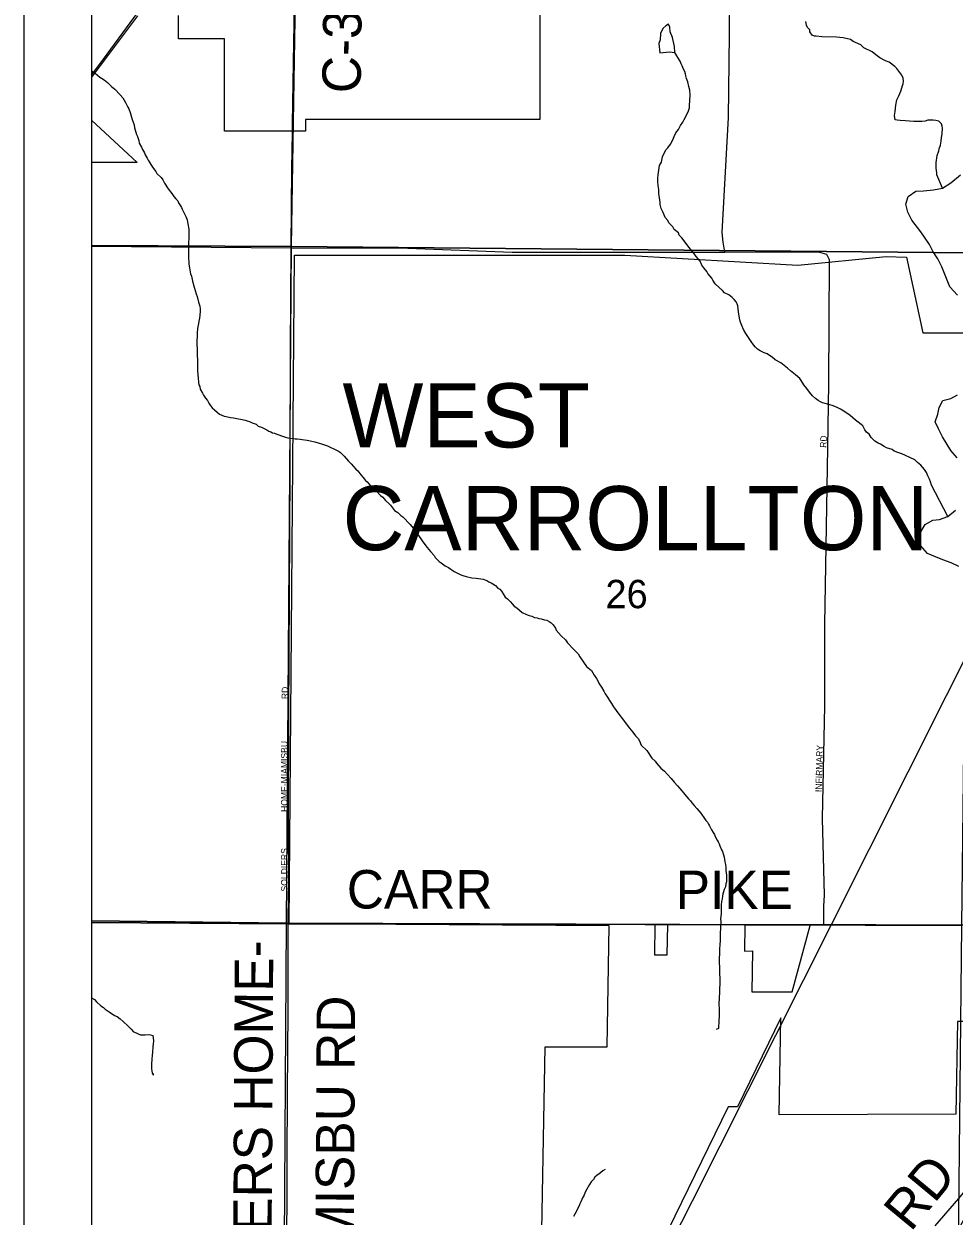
# Model space of a CAD drawing. Extents: x -209 to 4852, y 0 to 905.
# Drawn here: x 433.77 to 461.25, y 254.75 to 289.97 of the extents above; entities that cross this region are included whole.
import ezdxf

# ---------------------------------------------------------------- set-up
doc = ezdxf.new("R2010")
doc.units = 0
for name, color, linetype in [('Default', 7, 'Continuous'), ('GM_P_County_Alignment', 7, 'Continuous'), ('GM_X_Airport_Location_Class_2', 7, 'Continuous'), ('GM_X_Airport_Location_Class_3', 7, 'Continuous'), ('GM_X_Corporation_Text', 7, 'Continuous'), ('GM_X_County_Road', 7, 'Continuous'), ('GM_X_County_Road_Text', 7, 'Continuous'), ('GM_X_County_Subdivision_Text', 7, 'Continuous'), ('GM_X_Minor_Lake_Text', 7, 'Continuous'), ('GM_X_Minor_River', 7, 'Continuous'), ('GM_X_Township_Road_Text', 7, 'Continuous'), ('GM_X_US_Location', 7, 'Continuous'), ('GM_X_US_Route', 7, 'Continuous'), ('SH_Data', 7, 'Continuous')]:
    doc.layers.add(name, color=color, linetype=linetype)

msp = doc.modelspace()

# ---------------------------------------------------------------- linework, layer by layer
at = {"layer": 'Default'}
msp.add_lwpolyline([(571.768, 202.559), (571.768, 338.559), (435.768, 338.559), (435.768, 202.559)], close=True, dxfattribs=at)
at = {"layer": 'GM_X_Airport_Location_Class_2'}
for points in [[(454.478, 283.232), (454.434, 283.528), (454.404, 283.81), (454.583, 287.205), (454.62, 289.656), (454.639, 291.955), (454.657, 293.282), (454.655, 293.317)], [(441.671, 283.356), (441.689, 285.704), (441.706, 286.766)], [(435.768, 283.404), (441.671, 283.356), (445.118, 283.344), (448.196, 283.232), (451.618, 283.226), (454.478, 283.232)], [(441.582, 263.588), (441.598, 264.63), (441.587, 266.284), (441.602, 269.525), (441.62, 273.113), (441.632, 276.804), (441.647, 280.335), (441.671, 283.356)], [(457.569, 282.996), (457.569, 283.005), (457.496, 283.158), (457.285, 283.224), (454.478, 283.232)], [(457.401, 263.358), (457.408, 263.906), (457.422, 264.232), (457.369, 266.498), (457.429, 269.826), (457.431, 272.243), (457.481, 275.123), (457.519, 277.448), (457.554, 279.348), (457.569, 282.985), (457.569, 282.996)], [(457.401, 263.358), (464.729, 263.345)]]:
    msp.add_lwpolyline(points, dxfattribs=at)
at = {"layer": 'GM_X_County_Road'}
for points in [[(452.847, 289.145), (453.006, 289.127), (452.994, 289.302), (452.931, 289.569), (452.859, 289.738), (452.854, 289.875), (452.818, 289.967), (452.733, 289.916), (452.647, 289.834), (452.576, 289.69)], [(460.91, 285.12), (460.741, 285.517), (460.742, 285.578), (460.736, 285.632), (460.723, 285.723), (460.718, 285.815), (460.72, 285.876), (460.729, 285.944), (460.746, 286.005), (460.756, 286.081), (460.805, 286.225), (460.814, 286.278), (460.847, 286.391), (460.866, 286.513), (460.884, 286.619), (460.902, 286.725), (460.906, 286.893), (460.9, 286.954), (460.879, 287.023), (460.797, 287.102), (460.714, 287.119), (460.63, 287.128), (460.554, 287.13), (460.478, 287.124), (460.393, 287.104), (460.301, 287.091), (460.195, 287.086), (460.065, 287.089), (459.936, 287.099), (459.814, 287.11), (459.662, 287.114), (459.57, 287.131), (459.51, 287.14), (459.49, 287.263), (459.508, 287.384), (459.528, 287.567), (459.563, 287.734), (459.62, 287.847), (459.676, 287.983), (459.726, 288.149), (459.751, 288.202), (459.76, 288.285), (459.747, 288.37), (459.711, 288.454), (459.653, 288.54), (459.564, 288.656), (459.497, 288.711), (459.333, 288.845), (459.227, 288.885), (459.062, 288.973), (458.942, 289.06), (458.83, 289.147), (458.589, 289.267), (458.5, 289.353), (458.266, 289.457), (458.191, 289.513), (457.971, 289.564), (457.781, 289.584), (457.347, 289.594), (457.18, 289.613), (457.126, 289.615), (457.058, 289.639), (456.992, 289.74), (456.986, 289.793), (456.919, 289.864), (456.891, 289.933), (456.871, 290.04)], [(452.576, 289.69), (452.572, 289.5), (452.532, 289.395), (452.557, 289.113), (452.847, 289.145)], [(452.568, 284.64), (452.57, 284.693), (452.556, 284.77), (452.531, 284.961), (452.532, 285.014), (452.526, 285.076), (452.506, 285.198), (452.502, 285.32), (452.497, 285.412), (452.507, 285.511), (452.535, 285.716), (452.552, 285.792), (452.608, 285.889), (452.617, 285.95), (452.642, 286.041), (452.739, 286.252), (452.794, 286.312), (452.873, 286.417), (452.945, 286.544), (452.986, 286.643), (453.035, 286.756), (453.113, 286.853), (453.17, 286.974), (453.241, 287.071), (453.273, 287.146), (453.362, 287.312), (453.41, 287.402), (453.435, 287.493), (453.437, 287.562), (453.448, 287.706), (453.452, 287.874), (453.441, 288.011), (453.413, 288.119), (453.386, 288.257), (453.351, 288.364), (453.33, 288.441), (453.316, 288.495), (453.295, 288.564), (453.258, 288.633), (453.215, 288.733), (453.186, 288.795), (453.165, 288.849), (453.006, 289.127)], [(435.768, 288.597), (435.797, 288.569), (435.872, 288.513), (436.014, 288.403), (436.067, 288.371), (436.142, 288.324), (436.239, 288.238), (436.358, 288.12), (436.455, 288.042), (436.611, 287.878), (436.692, 287.785), (436.773, 287.653), (436.838, 287.514), (436.867, 287.46), (436.91, 287.352), (436.965, 287.153), (437.03, 286.991)], [(437.03, 286.991), (437.035, 286.907), (437.078, 286.777), (437.099, 286.708), (437.128, 286.646), (437.163, 286.531), (437.176, 286.454), (437.242, 286.331), (437.27, 286.261), (437.329, 286.168), (437.35, 286.107), (437.409, 286.006), (437.438, 285.952), (437.489, 285.867), (437.569, 285.743), (437.665, 285.611), (437.702, 285.55), (437.828, 285.44), (437.872, 285.362), (437.923, 285.27), (438.033, 285.099), (438.136, 284.96), (438.203, 284.874), (438.254, 284.804), (438.314, 284.742), (438.335, 284.688), (438.401, 284.603), (438.431, 284.549), (438.444, 284.495), (438.488, 284.425), (438.553, 284.279), (438.589, 284.186), (438.616, 284.071), (438.643, 283.911), (438.646, 283.743), (438.643, 283.621), (438.633, 283.522), (438.637, 283.4), (438.632, 283.187), (438.637, 283.103), (438.635, 283.034), (438.641, 282.95), (438.646, 282.874), (438.667, 282.767), (438.693, 282.591), (438.721, 282.521), (438.748, 282.368), (438.797, 282.199), (438.86, 282), (438.889, 281.923), (438.93, 281.754), (438.965, 281.631), (438.978, 281.555), (438.976, 281.471), (438.956, 281.281), (438.938, 281.19), (438.929, 281.121), (438.902, 280.977), (438.891, 280.833), (438.883, 280.513), (438.886, 280.36), (438.885, 280.307), (438.888, 280.139), (438.895, 280.086), (438.899, 279.948), (438.897, 279.895), (438.901, 279.758), (438.912, 279.59), (438.918, 279.513), (438.93, 279.383), (438.943, 279.314), (438.965, 279.261), (438.978, 279.184), (439.051, 279.06), (439.08, 279.006), (439.131, 278.921), (439.19, 278.843), (439.234, 278.766), (439.271, 278.712), (439.337, 278.634), (439.397, 278.572), (439.479, 278.501), (439.546, 278.446), (439.682, 278.389), (439.742, 278.373), (439.871, 278.347), (439.962, 278.337), (440.114, 278.31), (440.167, 278.301), (440.311, 278.267), (440.364, 278.251), (440.44, 278.226), (440.515, 278.186), (440.628, 278.145), (440.696, 278.09), (440.794, 278.057), (440.846, 278.026), (440.952, 277.977), (441.004, 277.946), (441.065, 277.921), (441.118, 277.897)], [(461.356, 281.956), (461.127, 282.206), (460.892, 282.799), (460.776, 283.031), (460.637, 283.24), (460.529, 283.456), (460.273, 283.829), (460.008, 284.179), (459.885, 284.411), (459.831, 284.648), (459.898, 284.875), (460.123, 285.036), (460.344, 285.037), (460.642, 285.067), (460.91, 285.12), (461.157, 285.273), (461.446, 285.509)], [(461.071, 275.426), (460.588, 276.348), (460.552, 276.441), (460.523, 276.525), (460.48, 276.626), (460.437, 276.718), (460.378, 276.811), (460.319, 276.881), (460.267, 276.936), (460.17, 277.014), (460.096, 277.092), (459.945, 277.165), (459.817, 277.221), (459.704, 277.27), (459.621, 277.302), (459.485, 277.351), (459.425, 277.398), (459.251, 277.448), (459.191, 277.488), (459.079, 277.559), (459.011, 277.591), (458.913, 277.647), (458.802, 277.757), (458.743, 277.857), (458.669, 277.912), (458.617, 277.982), (458.559, 278.098), (458.507, 278.137), (458.417, 278.208), (458.342, 278.271), (458.26, 278.334), (458.178, 278.405), (457.998, 278.531), (457.901, 278.587), (457.795, 278.643), (457.675, 278.691), (457.554, 278.725), (457.448, 278.758), (457.365, 278.783), (457.304, 278.807), (457.237, 278.847), (457.162, 278.909), (457.073, 278.988), (456.984, 279.097), (456.903, 279.206), (456.814, 279.307), (456.733, 279.438), (456.697, 279.5), (456.57, 279.602), (456.421, 279.72), (456.331, 279.799), (456.137, 279.956), (455.964, 280.052), (455.89, 280.122), (455.725, 280.225), (455.642, 280.258), (455.521, 280.314), (455.446, 280.362), (455.387, 280.424), (455.327, 280.494), (455.254, 280.587), (455.18, 280.704), (455.1, 280.828), (455.034, 280.944), (454.984, 281.067), (454.941, 281.159), (454.92, 281.228), (454.893, 281.397), (454.88, 281.466), (454.862, 281.649), (454.848, 281.703), (454.811, 281.765), (454.752, 281.835), (454.693, 281.89), (454.596, 281.968), (454.468, 282.032), (454.408, 282.095), (454.311, 282.181), (454.192, 282.291), (454.126, 282.399), (454.09, 282.461), (453.979, 282.601), (453.95, 282.655), (453.861, 282.764), (453.803, 282.849), (453.752, 282.965), (453.634, 283.105), (453.56, 283.198), (453.427, 283.369), (453.206, 283.649), (453.132, 283.727), (453.11, 283.796), (452.983, 283.898), (452.947, 283.975), (452.828, 284.092), (452.792, 284.162), (452.718, 284.255), (452.675, 284.348), (452.646, 284.417), (452.595, 284.517), (452.568, 284.64)], [(461.347, 277.153), (461.155, 277.372), (460.914, 277.775), (460.791, 278.006), (460.698, 278.214), (460.773, 278.448), (460.816, 278.645), (460.921, 278.848), (461.159, 278.909), (461.352, 279.011)], [(441.118, 277.897), (441.17, 277.881), (441.246, 277.856), (441.299, 277.832), (441.382, 277.807), (441.435, 277.783), (441.495, 277.766), (441.564, 277.749), (441.64, 277.739), (441.715, 277.722), (441.784, 277.713), (441.845, 277.712), (441.928, 277.702), (441.989, 277.693), (442.141, 277.674), (442.278, 277.648), (442.361, 277.63), (442.467, 277.597), (442.595, 277.556), (442.739, 277.507), (442.822, 277.474), (442.95, 277.41), (443.063, 277.354), (443.123, 277.307), (443.182, 277.252), (443.234, 277.205), (443.36, 277.057), (443.442, 276.979), (443.575, 276.823), (443.635, 276.769), (443.723, 276.652), (443.79, 276.574), (443.864, 276.489), (443.916, 276.442), (444.012, 276.325), (444.065, 276.293), (444.302, 276.043), (444.37, 275.996), (444.458, 275.895), (444.548, 275.801), (444.6, 275.754), (444.718, 275.599), (444.815, 275.543), (444.904, 275.449), (444.964, 275.41), (445.18, 275.184), (445.357, 274.966), (445.408, 274.888), (445.541, 274.702), (445.614, 274.594), (445.688, 274.508), (445.732, 274.446), (445.784, 274.384), (445.895, 274.267), (445.925, 274.213), (446.043, 274.088), (446.096, 274.056), (446.215, 273.962), (446.313, 273.913), (446.478, 273.795), (446.538, 273.763), (446.659, 273.707), (446.734, 273.682), (446.832, 273.649), (447.007, 273.614), (447.136, 273.604), (447.205, 273.594), (447.273, 273.578), (447.341, 273.568), (447.447, 273.528), (447.507, 273.488), (447.575, 273.463), (447.627, 273.432), (447.702, 273.384), (447.777, 273.306), (447.829, 273.274), (447.881, 273.212), (447.932, 273.135), (447.991, 273.042), (448.058, 272.987), (448.147, 272.901), (448.192, 272.846), (448.251, 272.776), (448.333, 272.721), (448.49, 272.587), (448.618, 272.531), (448.701, 272.498), (448.777, 272.474), (448.86, 272.441), (448.936, 272.424), (448.988, 272.408), (449.057, 272.398), (449.155, 272.373), (449.223, 272.356), (449.291, 272.316), (449.351, 272.277), (449.403, 272.222), (449.477, 272.121), (449.498, 272.06), (449.646, 271.896), (449.773, 271.779)], [(461.389, 273.948), (461.163, 274.053), (460.922, 274.144), (460.704, 274.234), (460.462, 274.324), (460.263, 274.566), (460.185, 274.758), (460.283, 274.991), (460.402, 275.186), (460.626, 275.309), (460.825, 275.334), (461.071, 275.426), (461.289, 275.61)], [(449.773, 271.779), (449.832, 271.693), (450.017, 271.491), (450.143, 271.366), (450.194, 271.273), (450.393, 270.994), (450.542, 270.868), (450.623, 270.737), (450.689, 270.636), (450.725, 270.567), (450.768, 270.482), (450.834, 270.381), (450.9, 270.257), (450.944, 270.18), (451.01, 270.087), (451.068, 269.987), (451.127, 269.901), (451.193, 269.801), (451.266, 269.692), (451.347, 269.583), (451.451, 269.444), (451.561, 269.296), (451.664, 269.164), (451.761, 269.055), (451.842, 268.946), (451.916, 268.861), (451.96, 268.799), (452.01, 268.668), (452.173, 268.504), (452.32, 268.287), (452.425, 268.193), (452.461, 268.131), (452.587, 267.983), (452.699, 267.897), (452.788, 267.795), (452.892, 267.679), (452.98, 267.57), (453.077, 267.468), (453.151, 267.39), (453.21, 267.32), (453.254, 267.258), (453.343, 267.149), (453.402, 267.079), (453.462, 267.017), (453.506, 266.963), (453.572, 266.885), (453.647, 266.799), (453.765, 266.659), (453.883, 266.504), (453.919, 266.442), (453.964, 266.387), (453.993, 266.333), (454.03, 266.279), (454.088, 266.163), (454.131, 266.086), (454.175, 266.024), (454.197, 265.97), (454.255, 265.862), (454.277, 265.808), (454.313, 265.747), (454.335, 265.693), (454.385, 265.577), (454.414, 265.523), (454.442, 265.423), (454.455, 265.354), (454.469, 265.293), (454.483, 265.224), (454.496, 265.14), (454.508, 265.041), (454.506, 264.965), (454.526, 264.827), (454.531, 264.751), (454.528, 264.629), (454.511, 264.568), (454.494, 264.485), (454.461, 264.402), (454.444, 264.334), (454.42, 264.273), (454.41, 264.205), (454.401, 264.129), (454.383, 264.046), (454.374, 263.954), (454.367, 263.695), (454.357, 263.604), (454.355, 263.536), (454.36, 263.444), (454.355, 263.246), (454.344, 263.125), (454.339, 262.911), (454.327, 262.744), (454.317, 262.668), (454.323, 262.599), (454.315, 262.272), (454.317, 262.081), (454.323, 261.998), (454.321, 261.937), (454.332, 261.754), (454.321, 261.335), (454.311, 261.228), (454.304, 260.985), (454.31, 260.908)], [(435.768, 261.206), (435.858, 261.153), (435.918, 261.083), (436.044, 260.965), (436.119, 260.918), (436.171, 260.871), (436.231, 260.824), (436.291, 260.792), (436.449, 260.681), (436.524, 260.649), (436.614, 260.586), (436.703, 260.507), (436.852, 260.367), (436.941, 260.281), (437.008, 260.203), (437.083, 260.171), (437.144, 260.139)], [(454.31, 260.908), (454.308, 260.832), (454.313, 260.741), (454.306, 260.459), (454.296, 260.375), (454.287, 260.299), (454.225, 260.271)], [(437.144, 260.139), (437.212, 260.114), (437.356, 260.111), (437.448, 260.116), (437.509, 260.114), (437.577, 260.09), (437.59, 260.021), (437.603, 259.929), (437.593, 259.831), (437.584, 259.762), (437.572, 259.587), (437.562, 259.519), (437.551, 259.382), (437.54, 259.253), (437.538, 259.177), (437.544, 259.108), (437.55, 259.047), (437.563, 258.978), (437.6, 258.916), (437.594, 258.977)], [(450.946, 256.13), (450.877, 256.094), (450.76, 255.99), (450.706, 255.968), (450.643, 255.901), (450.596, 255.834), (450.533, 255.767), (450.485, 255.684), (450.405, 255.549), (450.357, 255.459), (450.309, 255.354), (450.277, 255.293), (450.252, 255.241), (450.228, 255.18), (450.196, 255.113), (450.163, 255.037), (450.043, 254.812), (450.011, 254.744)]]:
    msp.add_lwpolyline(points, dxfattribs=at)
at = {"layer": 'GM_X_County_Road_Text'}
msp.add_line((435.768, 263.429), (441.579, 263.388), dxfattribs=at)
for points in [[(441.706, 286.766), (441.71, 287.017), (441.75, 289.423), (441.809, 292.74), (441.828, 293.584), (441.902, 296.752)], [(441.579, 263.388), (441.579, 263.388), (441.582, 263.588)], [(441.486, 247.232), (441.481, 247.741), (441.511, 250.955), (441.538, 253.158), (441.544, 256.397), (441.56, 258.376), (441.578, 260.827), (441.579, 263.388)], [(441.579, 263.388), (457.401, 263.358)], [(460.692, 254.469), (461.393, 255.273), (461.955, 255.952), (462.419, 256.656), (462.689, 257.197), (463.115, 257.925), (463.541, 258.66), (463.695, 259.067), (463.895, 259.86), (464.175, 261.069), (464.205, 261.199)]]:
    msp.add_lwpolyline(points, dxfattribs=at)
at = {"layer": 'GM_X_County_Subdivision_Text'}
msp.add_lwpolyline([(435.768, 288.457), (436.119, 288.932), (437.018, 290.155), (437.694, 291.066), (438.596, 292.294), (439.709, 293.791), (440.918, 295.394), (441.442, 296.087), (441.902, 296.752)], dxfattribs=at)
at = {"layer": 'GM_X_Minor_Lake_Text'}
for points in [[(435.768, 338.559), (435.768, 263.429), (441.579, 263.388), (464.729, 263.345)], [(464.729, 263.345), (441.579, 263.388), (435.768, 263.429), (435.768, 202.559)]]:
    msp.add_lwpolyline(points, dxfattribs=at)
at = {"layer": 'GM_X_Minor_River'}
for points in [[(435.768, 303.574), (435.768, 283.431), (441.676, 283.395), (442.006, 303.553)], [(442.006, 303.553), (462.61, 303.563), (461.7, 283.212), (441.676, 283.395)], [(435.768, 283.431), (435.768, 263.479), (441.524, 263.407), (441.676, 283.395)], [(441.676, 283.395), (461.7, 283.212), (461.475, 263.34), (441.524, 263.407)], [(435.768, 263.479), (435.768, 243.073), (441.402, 243.01), (441.524, 263.407)], [(441.524, 263.407), (461.475, 263.34), (461.375, 253.828), (454.651, 242.994), (441.402, 243.01)]]:
    msp.add_lwpolyline(points, close=True, dxfattribs=at)
at = {"layer": 'GM_X_US_Location'}
for points in [[(449.017, 291.242), (449.017, 287.148), (442.085, 287.147), (442.085, 286.806), (439.699, 286.806), (439.699, 289.535), (438.335, 289.535), (438.335, 290.218)], [(437.129, 290.207), (435.768, 288.403), (435.768, 287.124), (437.113, 285.875), (435.768, 285.875), (435.768, 263.429), (441.609, 263.388), (441.765, 283.139), (451.528, 283.141), (456.634, 282.846), (459.242, 283.106), (459.842, 283.084), (460.326, 280.845), (461.581, 280.845)], [(449.018, 251.076), (449.17, 259.757), (451.003, 259.757), (451.066, 263.329), (441.609, 263.388), (441.765, 283.139), (451.528, 283.141), (456.634, 282.846), (459.242, 283.106), (459.842, 283.084), (460.326, 280.845), (461.581, 280.845)], [(460.111, 251.937), (462.499, 256.47), (463.71, 258.641), (464.182, 260.5), (461.353, 260.505), (461.305, 257.767), (456.084, 257.75), (456.134, 260.611), (454.851, 257.981), (454.575, 257.981), (451.226, 251.115)]]:
    msp.add_lwpolyline(points, dxfattribs=at)
for points in [[(452.415, 263.359), (452.399, 262.469), (452.778, 262.469), (452.793, 263.358)], [(455.07, 263.349), (455.056, 262.583), (455.299, 262.591), (455.278, 261.379), (456.232, 261.379), (456.472, 261.379), (456.996, 263.341)]]:
    msp.add_lwpolyline(points, close=True, dxfattribs=at)
at = {"layer": 'GM_X_US_Route'}
msp.add_lwpolyline([(451.952, 252.1), (453.519, 255.209), (457.616, 263.348), (461.024, 270.137), (463.171, 274.403)], dxfattribs=at)
at = {"layer": 'SH_Data'}
for p, q in [((433.768, 340.559), (433.768, 200.559)), ((435.768, 338.559), (435.768, 202.559))]:
    msp.add_line(p, q, dxfattribs=at)

# ---------------------------------------------------------------- texts
at = {"layer": 'GM_P_County_Alignment'}
for s, height, rotation, p in [('C-37', 1.1364, 89.3142, (443.719, 287.92)), ('CARR', 1.1364, 0, (443.311, 263.841)), ('PIKE', 1.1364, 0, (453.028, 263.824)), ('SOLDIERS HOME-', 1.13636, 89.6699, (441.064, 249.73)), ('MIAMISBU RD', 1.13636, 89.6951, (443.503, 251.135)), ('RD', 1.1364, 50.3726, (459.968, 254.264))]:
    msp.add_text(s, height=height, rotation=rotation, dxfattribs=at).set_placement(p)
at = {"layer": 'GM_X_Airport_Location_Class_3'}
for s, height, rotation, p in [('RD', 0.1894, 87.1392, (457.477, 277.446)), ('RD', 0.1894, 90, (441.576, 270.027)), ('HOME-MIAMISBU', 0.18939, 90, (441.559, 266.694)), ('INFIRMARY', 0.1894, 88.532, (457.343, 267.278)), ('SOLDIERS', 0.1894, 90, (441.559, 264.344))]:
    msp.add_text(s, height=height, rotation=rotation, dxfattribs=at).set_placement(p)
at = {"layer": 'GM_X_Corporation_Text'}
for s, p in [('WEST', (443.183, 277.461)), ('CARROLLTON', (443.183, 274.426))]:
    msp.add_text(s, height=1.8939, rotation=0, dxfattribs=at).set_placement(p)
at = {"layer": 'GM_X_Township_Road_Text'}
msp.add_text('26', height=0.8371, rotation=0, dxfattribs=at).set_placement((450.953, 272.712))

doc.saveas('drawing.dxf')
